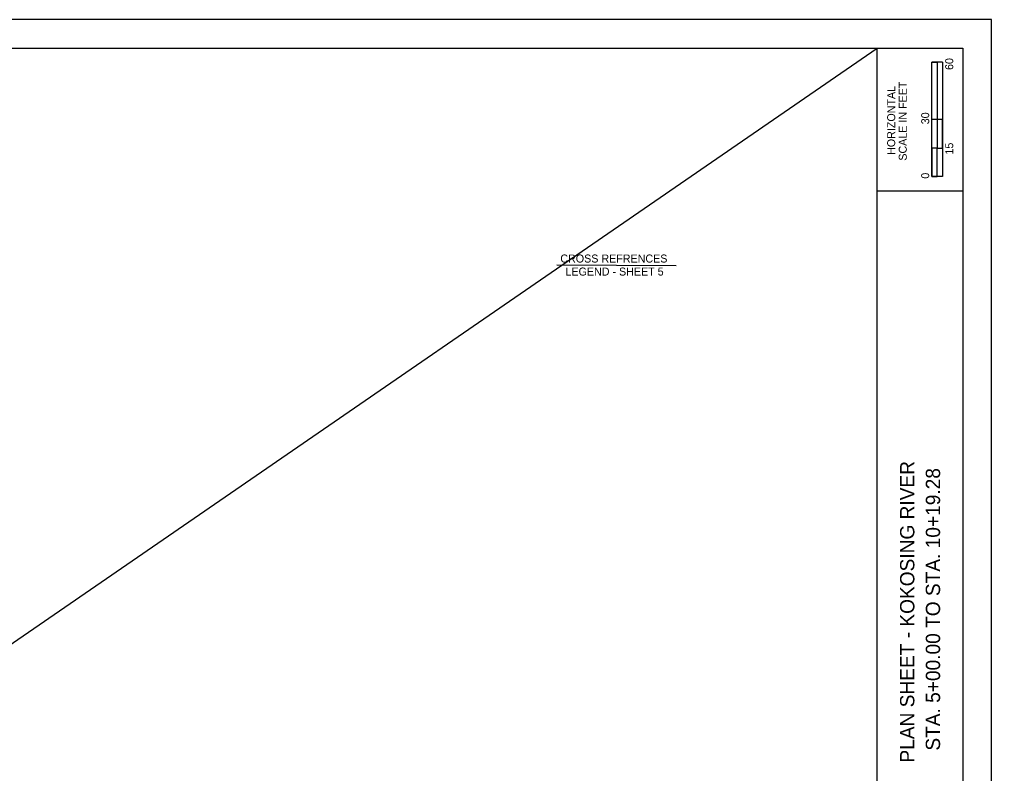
# Model space of a CAD drawing. Extents: x -17 to 34, y -2.3 to 22.
# Drawn here: x 17 to 34, y 8.81 to 22 of the extents above; entities that cross this region are included whole.
import ezdxf

# ---------------------------------------------------------------- set-up
doc = ezdxf.new("R2010")
doc.units = 0
for name, color, linetype in [('CS-ALGN-TEXT', 7, 'Continuous'), ('CS-ANNO', 7, 'Continuous'), ('CS-ANNO-MATC', 7, 'Continuous'), ('CS-ANNO-MATC-TEXT', 7, 'Continuous'), ('CS-PROF-TEXT', 7, 'Continuous')]:
    doc.layers.add(name, color=color, linetype=linetype)

msp = doc.modelspace()

# ---------------------------------------------------------------- linework, layer by layer
at = {"layer": 'CS-ALGN-TEXT'}
msp.add_lwpolyline([(0, 0), (34, 0), (34, 22), (0, 22)], close=True, dxfattribs=at)
at = {"layer": 'CS-ANNO'}
for p, q in [((32, 0.5), (32, 21.5)), ((32, 19), (33.5, 19))]:
    msp.add_line(p, q, dxfattribs=at)
msp.add_lwpolyline([(1.5, 21.5), (33.5, 21.5), (33.5, 0.5), (1.5, 0.5)], close=True, dxfattribs=at)
at = {"layer": 'CS-ANNO-MATC'}
for p, q in [((32.957, 19.25), (32.957, 21.25)), ((33.144, 21.25), (32.957, 21.25)), ((32.957, 20.25), (32.957, 21.25)), ((32.957, 21.25), (33.05, 21.25)), ((33.05, 21.25), (33.051, 21.25)), ((33.051, 21.25), (33.051, 20.25)), ((33.144, 21.25), (33.144, 19.25)), ((33.051, 20.25), (32.957, 20.25)), ((33.143, 20.25), (33.05, 20.25)), ((33.05, 20.25), (33.05, 19.75)), ((33.143, 19.75), (33.143, 20.25)), ((33.05, 19.75), (32.957, 19.75)), ((32.957, 19.75), (32.957, 19.25)), ((33.05, 19.25), (33.05, 19.75)), ((33.05, 19.75), (33.143, 19.75)), ((33.144, 19.25), (32.957, 19.25)), ((32.957, 19.25), (33.05, 19.25))]:
    msp.add_line(p, q, dxfattribs=at)
at = {"layer": 'CS-ANNO-MATC-TEXT'}
msp.add_line((26.399, 17.704), (28.482, 17.698), dxfattribs=at)
at = {"layer": 'CS-PROF-TEXT'}
msp.add_line((1.5, 0.5), (32, 21.5), dxfattribs=at)

# ---------------------------------------------------------------- texts
at = {"layer": 'CS-ANNO-MATC'}
for s, height, p in [('60', 0.14, (33.33, 21.116)), ('HORIZONTAL', 0.14, (32.315, 19.63)), ('SCALE IN FEET', 0.14, (32.517, 19.529)), ('30', 0.14, (32.91, 20.166)), ('15', 0.14, (33.33, 19.636)), ('0', 0.14, (32.91, 19.214)), ('PLAN SHEET - KOKOSING RIVER', 0.25, (32.65, 8.999)), ('STA. 5+00.00 TO STA. 10+19.28', 0.25, (33.1, 9.208))]:
    msp.add_text(s, height=height, rotation=90, dxfattribs=at).set_placement(p)
at = {"layer": 'CS-ANNO-MATC-TEXT'}
for s, p in [('CROSS REFRENCES', (26.459, 17.747)), ('LEGEND - SHEET 5', (26.549, 17.519))]:
    msp.add_text(s, height=0.14, dxfattribs=at).set_placement(p)

doc.saveas('drawing.dxf')
